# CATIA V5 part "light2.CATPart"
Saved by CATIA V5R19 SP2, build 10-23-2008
Part number: light2
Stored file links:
  C:\BEHROOZ\catia learning\tarh haye mashin\hb\light2.CATPart
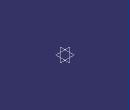
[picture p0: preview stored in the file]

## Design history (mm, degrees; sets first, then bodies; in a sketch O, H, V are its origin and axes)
Body1 (main body)
  DatumPoint1
  Point1: (-155, 6, -8), relative to DatumPoint1
  DatumPoint2
  Point2: (-84, 29, 75), relative to DatumPoint2
  DatumPoint3
  Point3: (0, -22, -55), relative to DatumPoint3
  DatumCurve1
  Point4: type OnCurve, Support DatumCurve1, Length 163.922
  Point5: (-11, -20, -22), relative to Point4
  DatumPoint4
  Point6: (-17, 0, -11), relative to DatumPoint4
  DatumCurve2
  Point7: type OnCurve, Support DatumCurve2, Ratio 0.5
  Point8: (-26, -5, -7), relative to Point7
  DatumPoint5
  DatumCurve3
  DatumPoint6
  DatumCurve4
  Curve1: Elements (DatumPoint6; Point3; Point5; Point6; DatumPoint5)
  Point9: (1, -2, -28), relative to Point3
  Point10: (0, -31, -75), relative to Point5
  Point11: (-16, -31, -27), relative to Point6
  Point12: (-38, -31, -21), relative to Point8
  DatumPoint7
  DatumCurve5
  DatumPoint8
  DatumCurve6
  DatumCurve7
  Point13: type OnCurve, Support DatumCurve7, Ratio 0.71
  DatumCurve8
  DatumPoint9
  DatumCurve9
  Curve2: Elements (DatumPoint9; Point2; Point9; Point10; Point13)
  DatumCurve10
  Join1: Elements DatumCurve10
  DatumCurve11
  Join2: Elements DatumCurve11
  Corner1: Element1 Join2, Element2 Join1, Radius 150, Direction (0, 0, 1)
  DatumCurve12
  DatumCurve13
  Join3: Elements (DatumCurve12; DatumCurve13)
  Split1: ToCut Join3, Cutting Corner1
  DatumCurve14
  Join4: Elements DatumCurve14
  Split2: ToCut Join4, Cutting vertex [face of DatumCurve11 | face of Corner1]
  DatumCurve15
  Join5: Elements DatumCurve15
  Split3: ToCut Join5, Cutting vertex [face of Corner1 | face of DatumCurve10]
  DatumSurface1
  DatumSurface2
  DatumCurve16 to DatumCurve24
  Fill1: Boundary (Curve2; DatumCurve20; DatumCurve22; DatumCurve23; DatumCurve24)
  Symmetry1: ToTransfor Fill1, Reference zx-plane
  Split4: ToCut Corner1, Cutting vertex [face of DatumCurve11 | face of Corner1]
  Split5: ToCut Split4, Cutting vertex [face of Corner1 | face of DatumCurve10]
